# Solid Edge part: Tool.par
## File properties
Author: Türk
Template: iso part.par
Last saved by: Türk
Revision: 24
Application: Solid Edge
Accuracy: 0,990
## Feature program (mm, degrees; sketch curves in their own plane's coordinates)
base feature "unnamed BaseFeature 1"
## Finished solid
Body 1: sheet body, 1 face, 4 edges, 4 vertices.
  Faces by surface: swept 1
  Edges by curve: line 2, spline 2
Body 2: sheet body, 2 faces, 7 edges, 6 vertices.
  Faces by surface: plane 1, swept 1
  Edges by curve: line 5, spline 2
Body 3: solid body, 51 faces, 155 edges, 106 vertices.
  Faces by surface: blend 18, swept 17, plane 9, cylinder 2, spline 2, torus 2, sphere 1
  Edges by curve: intersection 78, curve on surface 34, line 32, circle 9, spline 2
Bounding box of the edges (mm; curved faces can reach further): 1903.068 x 500.000 x 769.640, from (-425.4509, 1682.0301, -25) to (1477.6166, 2182.0301, 744.6402).
Cylindrical faces by radius (mm): R20.6875 x1, R772.185 x1
Toroidal faces (ring radius, tube radius in mm): R75 r25 x2
Spherical faces by radius (mm): R20.6875 x1
Planar faces by outward normal: +x 2, +y 1, -x 2, -y 1, -z 1, oblique 2
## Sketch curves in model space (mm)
line (148.9201, 2197.09, 25) -> (543.2456, 1666.9703, 25)
line (543.2456, 2197.09, 25) -> (148.9201, 1666.9703, 25)
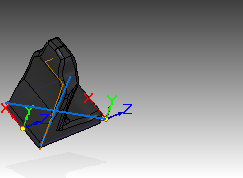
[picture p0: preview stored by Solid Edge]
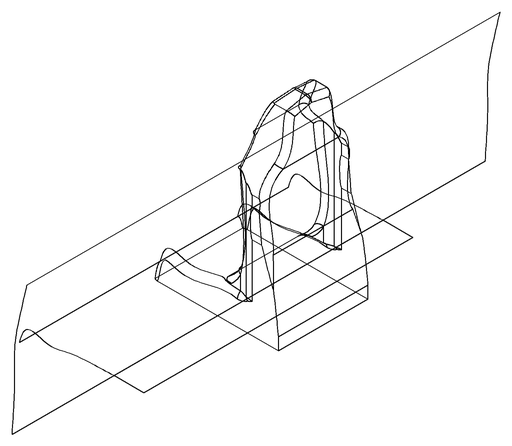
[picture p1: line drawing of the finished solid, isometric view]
